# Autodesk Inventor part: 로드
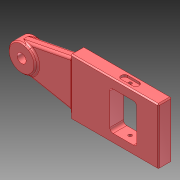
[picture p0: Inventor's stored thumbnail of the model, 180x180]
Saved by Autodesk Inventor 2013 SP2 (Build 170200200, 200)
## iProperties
Created: 2025-04
Part Number: 로드
Material: Generic
Document SubType Name: Modeling
Designer: 601
Density: 1 g/cm^3
Author: 601
변환 표준: STEP AP214IS
전처리기: Build: 200, Release: 2013 SP2 Update 6 - Date: Thu 07/17/2014
전송 단위: 밀리미터
불확실성: 0.01
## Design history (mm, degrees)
node "로드1"
node "솔리드1"
node "기준1"
